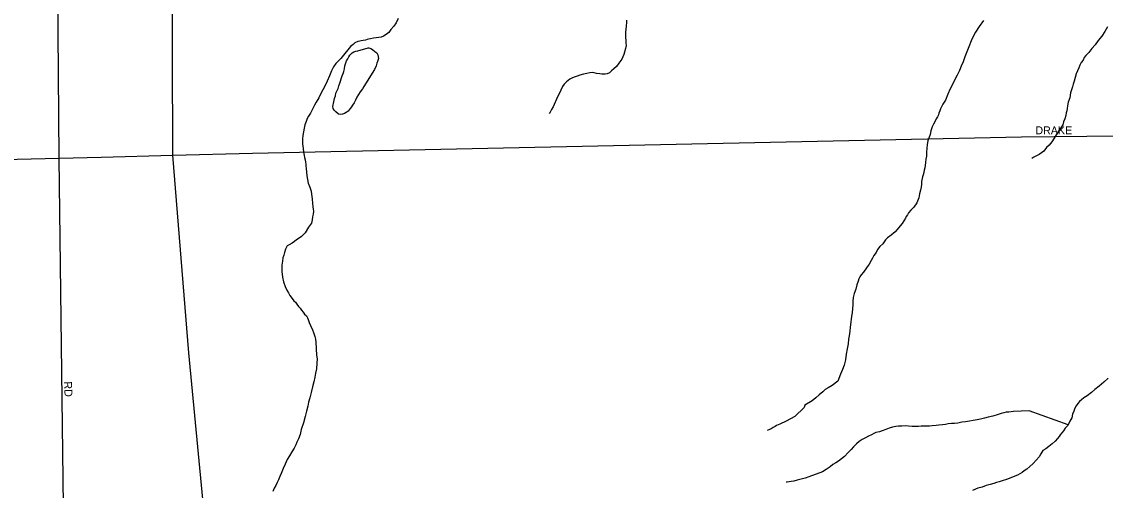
# Model space of a CAD drawing. Extents: x 2010165 to 2382125, y 1060529 to 1407316.
# Drawn here: x 2157707 to 2164475, y 1197412 to 1200338 of the extents above; entities that cross this region are included whole.
import ezdxf

# ---------------------------------------------------------------- set-up
doc = ezdxf.new("R2010")
doc.units = 0
for name, color, linetype in [('GM_X_City_Street', 7, 'Continuous'), ('GM_X_City_Street_Text', 7, 'Continuous'), ('GM_X_Interstate_Route', 7, 'Continuous'), ('GM_X_Minor_Lake', 7, 'Continuous'), ('GM_X_Minor_River', 7, 'Continuous')]:
    doc.layers.add(name, color=color, linetype=linetype)

msp = doc.modelspace()

# ---------------------------------------------------------------- linework, layer by layer
at = {"layer": 'GM_X_City_Street'}
for points in [[(2157941.4, 1199486.2), (2157928.1, 1201063)], [(2159147.8, 1199516.5), (2163951.3, 1199619.8), (2164563.3, 1199625.6), (2164789.3, 1199635), (2164858.5, 1199640.9), (2164968.9, 1199659.4)], [(2152235.3, 1199350.5), (2157941.4, 1199486.2)], [(2157941.4, 1199486.2), (2158203.6, 1199493.4)], [(2158006.9, 1194141.9), (2157941.4, 1199486.2)], [(2158203.6, 1199493.4), (2158651.4, 1199505.8), (2159147.8, 1199516.5)]]:
    msp.add_lwpolyline(points, dxfattribs=at)
at = {"layer": 'GM_X_Interstate_Route'}
msp.add_lwpolyline([(2159011, 1195551.5), (2158750.1, 1198271), (2158651.4, 1199505.8), (2158641.6, 1202700.9), (2158629.7, 1203536.7), (2158584.4, 1204122.4), (2158521.2, 1204759.7), (2158424.8, 1205308.8), (2158282.6, 1205916.9), (2158141.9, 1206518.8), (2157998.8, 1207038.5), (2157877.4, 1207533.2), (2157827.8, 1207693.8)], dxfattribs=at)
at = {"layer": 'GM_X_Minor_Lake'}
for points in [[(2159838.5, 1199924.2), (2159836, 1199919.5), (2159820.2, 1199901.3), (2159810.4, 1199883.1), (2159800.6, 1199866.9), (2159792.9, 1199848.8), (2159783.1, 1199832.6), (2159773.3, 1199816.4), (2159767.4, 1199806.3), (2159759.5, 1199796.2), (2159745.7, 1199780), (2159733.8, 1199771.8), (2159723.8, 1199765.6), (2159709.9, 1199761.5), (2159699.9, 1199759.3), (2159685.8, 1199761.2), (2159669.6, 1199775), (2159659.4, 1199786.9), (2159653.3, 1199796.9), (2159651.1, 1199808.9), (2159656.8, 1199837.1), (2159660.5, 1199859.2), (2159666.3, 1199875.3), (2159670.1, 1199891.4), (2159677.9, 1199909.5), (2159683.7, 1199921.7), (2159687.5, 1199937.8), (2159693.3, 1199953.9), (2159699.2, 1199966), (2159703, 1199982.1), (2159708.7, 1200000.2), (2159714.6, 1200014.3), (2159718.4, 1200026.4), (2159722.2, 1200044.5), (2159726, 1200062.6), (2159729.8, 1200074.7), (2159735.5, 1200094.8), (2159743.4, 1200107), (2159751.3, 1200119.1), (2159757.1, 1200129.2), (2159771, 1200143.4), (2159780.9, 1200149.6), (2159794.9, 1200153.8), (2159806.9, 1200155.9), (2159872, 1200175.6)], [(2159872, 1200175.6), (2159874.7, 1200174.8), (2159886.8, 1200170.9), (2159898.9, 1200165.1), (2159913.1, 1200153.2), (2159925.2, 1200143.3), (2159931.4, 1200131.3), (2159935.7, 1200109.3), (2159930, 1200089.2), (2159926.1, 1200079.1), (2159920.3, 1200063), (2159910.6, 1200040.8), (2159896.8, 1200016.6), (2159838.5, 1199924.2)]]:
    msp.add_lwpolyline(points, dxfattribs=at)
at = {"layer": 'GM_X_Minor_River'}
for points in [[(2160058.7, 1200357.6), (2160045, 1200331.4), (2160031.2, 1200311.1), (2160013.5, 1200288.9), (2159999.7, 1200270.6), (2159983.8, 1200258.4), (2159965.9, 1200248.1), (2159952, 1200242), (2159938, 1200239.8), (2159922, 1200237.6), (2159904, 1200235.3), (2159886, 1200231.1), (2159874, 1200229), (2159864, 1200226.8), (2159854.1, 1200222.7), (2159840.1, 1200220.5), (2159828.1, 1200218.4), (2159818.1, 1200216.2), (2159806.1, 1200214.1), (2159788.2, 1200205.8), (2159776.3, 1200195.7)], [(2161483.3, 1200347), (2161483.5, 1200335), (2161481.8, 1200310.9), (2161480, 1200290.8), (2161478.3, 1200272.7), (2161478.5, 1200256.7), (2161478.7, 1200238.6), (2161480.9, 1200220.6), (2161481.1, 1200206.6), (2161481.3, 1200190.5), (2161477.6, 1200170.4), (2161468, 1200134.2), (2161454.4, 1200103.9), (2161436.7, 1200079.6), (2161420.9, 1200059.4), (2161405.1, 1200043.1), (2161391.3, 1200030.9), (2161377.4, 1200018.7), (2161363.5, 1200012.5), (2161351.5, 1200010.4), (2161341.4, 1200010.2), (2161329.4, 1200010.1), (2161317.4, 1200011.9), (2161297.3, 1200015.7), (2161283.2, 1200019.6), (2161269.2, 1200021.4), (2161255.2, 1200019.2), (2161237.2, 1200015), (2161215.2, 1200010.7), (2161193.3, 1200004.4), (2161175.3, 1199998.2), (2161157.4, 1199991.9), (2161143.4, 1199985.7), (2161129.5, 1199979.5), (2161109.7, 1199963.2), (2161095.8, 1199949), (2161084, 1199932.8), (2161074.3, 1199910.6), (2161064.6, 1199888.4), (2161052.8, 1199868.2), (2161025.5, 1199807.7), (2161015.8, 1199789.5), (2161008, 1199773.4), (2161002.1, 1199765.3)], [(2163713.2, 1200346.3), (2163687.6, 1200307.9)], [(2163687.6, 1200307.9), (2163664, 1200273.5), (2163648.4, 1200245.2), (2163636.7, 1200219), (2163621.2, 1200180.7), (2163609.6, 1200150.4), (2163598, 1200118.2), (2163586.3, 1200087.9), (2163574.7, 1200059.7), (2163563, 1200033.5), (2163549.3, 1200005.2), (2163506.4, 1199918.4), (2163490.8, 1199886.1), (2163477.3, 1199847.8), (2163459.6, 1199823.6), (2163451.8, 1199807.4), (2163445.9, 1199793.3), (2163440.1, 1199781.2), (2163434.3, 1199767.1), (2163432.4, 1199757), (2163426.5, 1199744.9), (2163418.7, 1199730.8), (2163410.9, 1199716.6), (2163401.1, 1199698.4), (2163393.3, 1199682.3), (2163389.4, 1199670.2), (2163385.6, 1199656.1), (2163379.9, 1199634), (2163372.2, 1199611.8), (2163366.4, 1199593.7), (2163362.7, 1199571.6), (2163359, 1199547.4), (2163357.3, 1199525.4), (2163357.6, 1199499.3), (2163353.9, 1199479.2), (2163352.1, 1199459.1), (2163350.4, 1199441), (2163346.6, 1199424.9), (2163342.8, 1199410.8), (2163340.9, 1199396.8), (2163337.1, 1199382.6), (2163333.3, 1199370.6), (2163331.4, 1199358.5), (2163327.6, 1199340.4), (2163325.9, 1199324.3), (2163324.1, 1199304.2), (2163320.3, 1199286.1), (2163314.6, 1199264), (2163309, 1199237.8), (2163297.3, 1199207.6), (2163279.7, 1199179.3), (2163259.9, 1199161), (2163246.1, 1199144.8), (2163238.2, 1199132.6), (2163230.3, 1199122.5), (2163226.4, 1199112.4), (2163216.7, 1199094.3), (2163204.9, 1199078.1), (2163161.5, 1199025.4), (2163137.7, 1199005), (2163113.9, 1198988.7), (2163102, 1198976.5), (2163084.3, 1198952.2), (2163066.5, 1198933.9), (2163052.7, 1198915.7), (2163042.9, 1198897.5), (2163029.2, 1198879.3), (2163021.4, 1198861.1), (2163011.5, 1198847), (2162999.8, 1198824.8), (2162984.1, 1198800.5), (2162964.4, 1198774.1), (2162950.6, 1198757.9), (2162940.7, 1198745.8), (2162934.9, 1198733.7), (2162931.1, 1198717.6), (2162923.4, 1198695.4), (2162915.7, 1198667.2), (2162906.1, 1198641), (2162900.4, 1198616.9), (2162898.7, 1198592.8), (2162897, 1198570.7), (2162895.3, 1198546.6), (2162893.6, 1198520.5), (2162889.9, 1198500.4), (2162888.1, 1198480.3), (2162886.3, 1198464.2), (2162882.6, 1198446.1), (2162880.8, 1198430), (2162879.1, 1198405.9), (2162877.3, 1198391.9), (2162875.5, 1198375.8), (2162871.7, 1198355.7), (2162868.1, 1198327.6), (2162862.5, 1198295.4), (2162856.9, 1198263.2), (2162851.4, 1198227), (2162843.8, 1198192.8), (2162834.1, 1198166.6), (2162820.5, 1198138.4), (2162805, 1198094)], [(2164489, 1200305.7), (2164471.4, 1200277.4), (2164451.8, 1200247), (2164430.1, 1200220.7), (2164410.4, 1200194.4), (2164390.7, 1200170.1), (2164370.9, 1200145.7), (2164353.1, 1200127.4), (2164343.3, 1200115.3), (2164335.5, 1200097.1), (2164323.7, 1200083), (2164315.9, 1200066.8), (2164308.1, 1200050.7), (2164292.5, 1200012.3), (2164286.8, 1199990.2), (2164279.1, 1199966), (2164273.4, 1199947.9), (2164269.6, 1199931.8), (2164263.8, 1199913.7), (2164258, 1199893.6), (2164252.4, 1199863.4), (2164242.8, 1199835.2), (2164239.1, 1199813.1), (2164235.3, 1199797), (2164233.5, 1199780.9), (2164229.6, 1199768.8), (2164227.8, 1199752.7), (2164222.1, 1199732.6), (2164214.3, 1199712.4), (2164208.6, 1199694.3), (2164183, 1199653.9), (2164175.2, 1199643.7), (2164167.3, 1199631.6), (2164155.5, 1199611.4)], [(2159776.3, 1200195.7), (2159760.4, 1200183.4), (2159744.7, 1200163.2), (2159725, 1200138.8), (2159699.3, 1200108.4), (2159669.6, 1200078), (2159653.9, 1200055.7), (2159642.2, 1200031.5), (2159628.6, 1200001.2), (2159615, 1199967), (2159597.4, 1199930.6), (2159577.9, 1199894.3), (2159562.3, 1199862), (2159546.6, 1199835.7), (2159536.8, 1199817.5), (2159525.1, 1199795.3), (2159511.4, 1199767.1), (2159497.7, 1199748.8), (2159489.8, 1199734.7), (2159484.1, 1199714.6), (2159476.3, 1199694.4), (2159470.6, 1199674.2), (2159463.2, 1199628), (2159461.5, 1199605.9), (2159461.9, 1199575.8), (2159464.2, 1199545.8), (2159466.5, 1199523.7), (2159470.8, 1199503.7), (2159473, 1199489.7), (2159477.2, 1199475.7), (2159479.4, 1199461.7), (2159481.6, 1199447.7), (2159481.7, 1199437.6), (2159483.9, 1199421.6), (2159488.5, 1199375.5), (2159497.1, 1199329.5), (2159507.5, 1199305.5), (2159511.6, 1199293.6), (2159515.8, 1199279.6), (2159516.1, 1199261.5), (2159520.5, 1199231.5), (2159522.8, 1199203.4), (2159525.1, 1199181.4), (2159527.3, 1199167.3), (2159529.5, 1199155.3), (2159527.7, 1199137.2), (2159523.9, 1199119.1), (2159522.2, 1199101.1), (2159516.4, 1199080.9), (2159498.7, 1199054.6), (2159477.1, 1199020.2), (2159455.4, 1198997.9), (2159439.5, 1198985.7), (2159423.6, 1198975.5), (2159411.7, 1198965.3), (2159395.8, 1198955.1), (2159378, 1198944.8), (2159366, 1198938.6), (2159354.3, 1198918.4), (2159348.5, 1198896.3), (2159344.7, 1198880.2), (2159338.9, 1198864.1), (2159335.2, 1198844), (2159331.5, 1198817.8), (2159332.1, 1198777.7), (2159336.5, 1198743.6), (2159342.9, 1198713.6), (2159353.3, 1198685.7), (2159363.6, 1198661.7), (2159373.9, 1198645.8), (2159382.1, 1198627.8), (2159396.4, 1198610), (2159406.6, 1198596), (2159416.7, 1198586.1), (2159424.9, 1198574.2), (2159435.1, 1198560.3), (2159447.2, 1198550.4), (2159455.4, 1198536.4), (2159465.6, 1198524.5), (2159473.8, 1198512.6), (2159485.9, 1198500.7), (2159492.1, 1198488.8), (2159496.3, 1198478.8), (2159502.5, 1198460.8), (2159510.8, 1198440.8), (2159523.1, 1198414.9), (2159529.4, 1198396.9), (2159533.5, 1198384.9), (2159537.7, 1198372.9), (2159541.9, 1198356.9), (2159544.2, 1198336.9), (2159549.2, 1198256.7), (2159551.6, 1198232.6), (2159549.9, 1198206.6), (2159548.4, 1198170.4), (2159542.7, 1198144.3), (2159537, 1198118.1), (2159531.4, 1198090), (2159523.8, 1198057.8), (2159514.2, 1198023.5), (2159506.7, 1197989.3)], [(2164155.5, 1199611.4), (2164139.8, 1199589.1), (2164124.1, 1199566.9), (2164108.2, 1199552.6), (2164090.5, 1199530.3), (2164060.7, 1199509.9), (2164028.9, 1199491.5), (2164015.4, 1199483.5)], [(2164491.7, 1198112.7), (2164466, 1198088.3), (2164436.3, 1198061.9), (2164408.5, 1198041.5), (2164388.7, 1198023.2), (2164360.9, 1198002.8), (2164341, 1197990.5), (2164325.2, 1197976.2), (2164313.3, 1197966.1), (2164303.4, 1197953.9), (2164291.6, 1197939.7), (2164283.8, 1197925.6), (2164278, 1197907.4), (2164270.3, 1197887.3), (2164264.5, 1197865.1), (2164252.8, 1197844.9), (2164241.1, 1197816.7), (2164223.3, 1197800.4), (2164213.5, 1197784.3), (2164203.6, 1197772.1), (2164191.8, 1197757.9), (2164185.9, 1197747.8), (2164176.1, 1197735.6), (2164160.3, 1197719.4), (2164142.4, 1197703.1), (2164122.6, 1197684.8), (2164102.8, 1197670.6), (2164084.9, 1197660.3), (2164079, 1197650.2), (2164071.1, 1197640.1), (2164061.4, 1197621.9), (2164043.6, 1197599.6), (2164023.9, 1197579.3), (2164002.1, 1197561), (2163984.2, 1197544.7), (2163968.3, 1197534.5), (2163954.4, 1197524.3), (2163940.5, 1197516.1), (2163926.6, 1197505.9), (2163856.9, 1197478.9), (2163830.9, 1197470.6), (2163811, 1197464.3), (2163795, 1197460.1), (2163779.1, 1197453.9), (2163755.1, 1197447.6), (2163731.1, 1197441.3), (2163705.2, 1197432.9), (2163679.3, 1197424.6), (2163645.4, 1197410.1)], [(2162805, 1198094), (2162769.3, 1198067.5), (2162743.5, 1198051.1), (2162725.6, 1198040.9), (2162709.7, 1198026.6), (2162687.9, 1198008.3), (2162666.1, 1197990), (2162644.3, 1197971.7), (2162598.6, 1197943), (2162592.8, 1197928.9), (2162535.4, 1197874), (2162481.7, 1197843.3), (2162441.9, 1197824.7), (2162422, 1197816.5), (2162412.1, 1197810.3), (2162400.1, 1197804.1), (2162388.2, 1197796), (2162374.2, 1197789.8), (2162362.3, 1197785.6)], [(2159506.7, 1197989.3), (2159499, 1197963.1), (2159493.3, 1197937), (2159485.7, 1197906.8), (2159478.1, 1197872.6), (2159466.6, 1197834.3), (2159453.1, 1197792), (2159445.6, 1197759.8), (2159435.9, 1197733.6), (2159426.1, 1197713.4), (2159418.3, 1197695.3), (2159408.6, 1197675.1), (2159394.9, 1197652.9), (2159379.2, 1197626.6), (2159365.4, 1197604.4), (2159351.8, 1197576.1), (2159340.1, 1197547.9), (2159328.5, 1197517.6), (2159318.8, 1197497.5), (2159311, 1197477.3), (2159303.2, 1197461.1), (2159293.4, 1197443), (2159283.6, 1197424.8), (2159275.9, 1197404.6)], [(2164242.9, 1197821.1), (2163999.5, 1197908.1), (2163949.4, 1197907.4), (2163901.4, 1197904.8), (2163871.4, 1197900.5), (2163855.4, 1197900.3), (2163841.4, 1197896.1), (2163823.4, 1197891.8), (2163799.5, 1197883.5), (2163771.6, 1197875.2), (2163743.6, 1197868.8), (2163719.6, 1197862.5), (2163695.7, 1197856.2), (2163673.7, 1197851.9), (2163601.7, 1197839), (2163577.7, 1197836.7), (2163553.7, 1197832.3), (2163533.7, 1197830.1), (2163513.7, 1197829.8), (2163493.7, 1197827.6), (2163475.7, 1197823.4), (2163457.7, 1197821.1), (2163435.7, 1197818.9), (2163417.7, 1197816.6), (2163393.7, 1197814.3), (2163375.7, 1197812.1), (2163363.7, 1197812), (2163353.7, 1197811.8), (2163339.6, 1197813.7), (2163323.6, 1197813.5), (2163307.6, 1197811.3), (2163291.6, 1197811.1), (2163281.5, 1197810.9), (2163267.5, 1197810.8), (2163245.5, 1197812.5), (2163225.4, 1197814.3), (2163203.4, 1197812), (2163183.4, 1197811.8), (2163165.3, 1197811.5), (2163145.4, 1197807.3), (2163125.4, 1197801), (2163103.5, 1197792.7), (2163081.5, 1197784.4), (2163063.6, 1197778.2), (2163041.6, 1197773.9), (2163029.7, 1197767.7), (2163013.8, 1197759.5), (2162995.8, 1197751.3), (2162976, 1197739), (2162956.1, 1197728.7), (2162938.2, 1197716.5), (2162920.3, 1197702.2), (2162902.5, 1197683.9), (2162886.7, 1197667.7), (2162869, 1197647.4), (2162845.2, 1197623), (2162827.4, 1197608.8), (2162807.6, 1197594.5), (2162791.7, 1197584.2), (2162773.8, 1197574), (2162755.9, 1197559.7), (2162732.1, 1197541.4), (2162708.3, 1197527), (2162622.5, 1197495.9), (2162600.6, 1197487.6), (2162574.6, 1197481.3), (2162550.7, 1197474.9), (2162528.7, 1197468.6), (2162512.7, 1197466.5), (2162500.7, 1197464.3), (2162486.7, 1197464.1), (2162480.7, 1197464.1)]]:
    msp.add_lwpolyline(points, dxfattribs=at)

# ---------------------------------------------------------------- texts
at = {"layer": 'GM_X_City_Street_Text'}
for s, rotation, p in [('DRAKE', 0.00001, (2164037.5, 1199634.8)), ('RD', 273.01099, (2157970.4, 1198090.9))]:
    msp.add_text(s, height=50, rotation=rotation, dxfattribs=at).set_placement(p)

doc.saveas('drawing.dxf')
